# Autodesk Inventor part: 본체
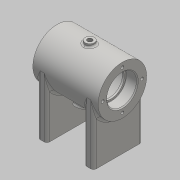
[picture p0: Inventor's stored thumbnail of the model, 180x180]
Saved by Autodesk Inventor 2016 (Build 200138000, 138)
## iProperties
Created: 2020-07
Part Number: 본체
Material: 일반
Document SubType Name: Modeling
Designer: user
Density: 1 g/cm^3
Appearance: 기본값
Mass: 113.055 g
Surface Area: 357.573 cm^2
Volume: 113.055 cm^3
Author: user
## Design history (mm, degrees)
sketch "스케치1"
  geometry: L1 (-30, -26)-(30, -26); L2 (30, -26)-(30, 26); L3 (30, 26)-(-30, 26); L4 (-30, 26)-(-30, -26); L5 (-30, -26)-(30, 26); L6 (30, -26)-(-30, 26); 1 further point
  constraints: 12 end point, 2 midpoint, 2 parallel, 1 horizontal, 1 perpendicular
  dimensions: "d0" = 60 distance of L2.end L3.end; "d1" = 52 distance of L3.end L1.start
extrude "돌출1" new body sketch "스케치1" distance "d2" = 64; taper "d3" = 0 deg
sketch "스케치2"
  geometry: L1 (0, 0)-(60, 0) reference; L2 (60, 0)-(60, 64) reference; L3 (0, 64)-(60, 64) reference; L4 (0, 0)-(0, 64) reference; L5 (10, 0)-(50, 0); L6 (50, 0)-(50, 64); L7 (50, 64)-(10, 64); L8 (10, 64)-(10, 0); 1 further point
  constraints: 8 end point, 2 parallel, 2 point on line, 1 horizontal, 1 perpendicular
  dimensions: "d4" = 20 distance of point (30, 0) L5.start; "d5" = 40 distance between parallel lines of L6 L8
extrude "돌출2" cut sketch "스케치2" stored distance "d6" = 64; taper "d7" = 0 deg
sketch "스케치3"
  geometry: L1 (35, 64)-(-35, 64); L2 (35, 64)-(35, 90); L3 (35, 90)-(-35, 90); L4 (-35, 90)-(-35, 64); 2 further points
  constraints: 8 end point, 2 perpendicular, 1 horizontal, 1 midpoint, 1 vertical, 1 vertical alignment
  dimensions: "d8" = 70 distance of L1.start L1.end; "d9" = 64 distance from line of point (0, 0) L1; "d10" = 52 diameter of L3 L1
revolve "회전1" sketch "스케치3" stored, may be unused: angle "d11" = 90 deg
sketch "스케치4"
  geometry: L1 (-20, 64)-(-20, 64) reference; L2 (-20, 64)-(-30, 64) reference; L3 (-30, 64)-(-30, 64) reference; L4 (-30, 64)-(-20, 64) reference; L5 (30, 64)-(20, 64) reference; L6 (20, 64)-(20, 64) reference; L7 (20, 64)-(30, 64) reference; L8 (30, 64)-(30, 64) reference; L9 (35, 38)-(35, 90) reference; L10 (-35, 38)-(-35, 90) reference; L11 (35, 64)-(-35, 64); L12 (35, 64)-(35, 80); L13 (35, 80)-(23, 80); L14 (23, 80)-(23, 78); L15 (23, 78)-(21, 78); L16 (21, 78)-(21, 85); L17 (21, 85)-(-21, 85); L18 (-21, 85)-(-21, 78); L19 (-21, 78)-(-23, 78); L20 (-23, 78)-(-23, 80); L21 (-23, 80)-(-35, 80); 1 further point
  constraints: 22 end point, 8 perpendicular, 2 midpoint, 2 point on line, 1 horizontal
  dimensions: "d12" = 12 distance of L12.end L13.end; "d13" = 2 distance of L14.end L15.end; "d14" = 42 distance of L16.end L17.end; "d15" = 12 distance of L20.end L21.end; "d16" = 32 diameter of L13 L11; "d17" = 28 diameter of L15 L11; "d18" = 42 diameter of L17 L11; "d19" = 28 diameter of L19 L11; "d20" = 32 diameter of L21 L11
revolve "회전2" sketch "스케치4" stored, may be unused: angle "d21" = 90 deg
node "작업 평면1"
sketch "스케치5"
  geometry: C1 r 5 at (0, 0); 1 further point
  constraints: 1 centre point, 1 coincident
  dimensions: "d23" = 10 diameter of C1
extrude "돌출3" join sketch "스케치5" stored distance "d24" = 64; taper "d25" = 0 deg
sketch "스케치6"
  geometry: L1 (0, 64)-(-9.919, 36.749); L2 (0, 64)-(0, 0); L3 (-9.919, 36.749)-(-15.557, 38.801); L4 (-15.557, 38.801)-(-14.291, 42.28); C1 r 16 at (0, 64) reference; A1 r 26 centre (0, 64) between (-14.291, 42.28) and (-8.893, 39.568)
  constraints: 8 end point, 2 perpendicular, 2 point on circle, 1 centre point, 1 coincident, 1 point on line, 1 vertical, 2 other
  dimensions: "d26" = 20 deg angle of L1 L2; "d27" = 29 distance of L1.start L1.end; "d28" = 12 diameter of L4 L1
revolve "회전3" sketch "스케치6" stored, may be unused: angle "d29" = 90 deg
sketch "스케치7"
  geometry: L1 (25, 20)-(-25, 20); L2 (-25, 20)-(-25, -20); L3 (-25, -20)-(25, -20); L4 (25, -20)-(25, 20); L5 (30, 26)-(30, -26) reference; L6 (-30, -26)-(-30, 26) reference; 1 further point
  constraints: 8 end point, 2 parallel, 1 horizontal, 1 perpendicular
  dimensions: "d30" = 5 distance between parallel lines of L5 L4; "d31" = 20 distance from line of point (0, 0) L3; "d32" = 40 distance between parallel lines of L1 L3; "d33" = 5 distance between parallel lines of L6 L2
hole "구멍1" sketch "스케치7" at (25, -20), (25, 20), (-25, 20), (-25, -20) diameter "d34" = 4.134; stored, may be unused: countersink angle "d38" = 90 deg, drill point angle "d40" = 118 deg; dims "d35" = 8, "d36" = 4, "d37" = 2, "d39" = 10
sketch "스케치8"
  geometry: L1 (0, 0)-(21, 0); C1 r 16 at (0, 0) reference; C2 r 26 at (0, 0) reference; 1 further point
  constraints: 2 end point, 1 horizontal
  dimensions: "d41" = 21 distance of L1.start L1.end
hole "구멍2" sketch "스케치8" at (21, 0) diameter "d42" = 3.242; stored, may be unused: countersink angle "d46" = 90 deg, drill point angle "d48" = 118 deg; dims "d43" = 8, "d44" = 4, "d45" = 2, "d47" = 10
sketch "스케치9"
  geometry: 1 further point
hole "구멍3" sketch "스케치9" at (0, 0) diameter "d52" = 5.188; stored, may be unused: countersink angle "d56" = 90 deg, drill point angle "d58" = 118 deg; dims "d53" = 12, "d54" = 4, "d55" = 2, "d57" = 16
sketch "스케치10"
  geometry: C1 r 6 at (0, 0) reference; 1 further point
hole "구멍4" sketch "스케치10" at (0, 0) diameter "d59" = 5.188; stored, may be unused: countersink angle "d63" = 90 deg, drill point angle "d65" = 118 deg; dims "d60" = 12, "d61" = 4, "d62" = 2, "d64" = 16
chamfer "모따기1" distance "d66" = 1; stored, may be unused: second distance "d67" = 2, angle "d68" = 45 deg
fillet "모깎기1" dims "d69" = 0.3
fillet "모깎기2" dims "d70" = 3
fillet "모깎기3" dims "d71" = 3
fillet "모깎기4" dims "d72" = 3
fillet "모깎기5" dims "d73" = 2
node "작업 평면2"
sketch "스케치11"
  geometry: L1 (-25, 19.379)-(-25, 22.621) reference; L2 (-35, -26)-(-35, 26) reference; L3 (-35, 26)-(35, 26) reference; 2 further points
  constraints: 1 other
  dimensions: "d74" = 35 distance from line of L2 point (0, 0); "d75" = 26 distance from line of L3 point (0, 0)
feature "엠보싱1" sketch "스케치11" dims "d0" = 60, "d1" = 52, "d76" = 0.5, "d77" = 0
node "솔리드1"
pattern_circular "원형 패턴1" dims angle "d50" = 360 deg
mirror "대칭1"
node "투영된 루프1"
node "투영된 루프2"
node "투영된 루프3"
node "투영된 루프4"
node "투영된 루프5"
other parameters: "d22" = 93
